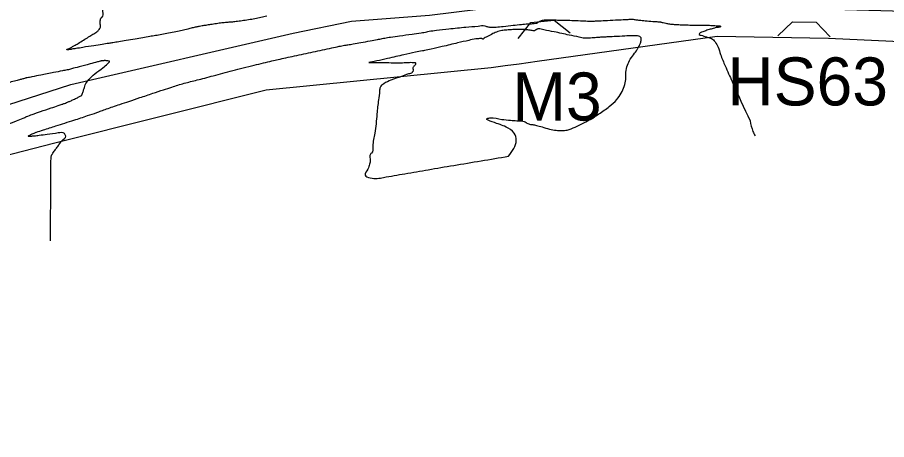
# Model space of a CAD drawing. Extents: x -478645 to -472650, y -1118147 to -1113892.
# Drawn here: x -477790.3 to -477609.4, y -1117492.2 to -1117404.3 of the extents above; entities that cross this region are included whole.
import ezdxf

# ---------------------------------------------------------------- set-up
doc = ezdxf.new("R2010")
doc.units = 0
for name, color, linetype in [('hospodářské sjezdy', 7, 'Continuous'), ('ObPÚ', 7, 'Continuous'), ('silnice', 7, 'Continuous'), ('TP_stavajicí_mosty', 7, 'Continuous'), ('Vrstevnice_vedlejsi', 7, 'Continuous')]:
    doc.layers.add(name, color=color, linetype=linetype)

msp = doc.modelspace()

# ---------------------------------------------------------------- linework, layer by layer
at = {"layer": 'hospodářské sjezdy'}
for p, q in [((-477632.071, -1117408.148), (-477629, -1117405.188)), ((-477629, -1117405.188), (-477624.116, -1117405.275)), ((-477624.116, -1117405.275), (-477621.152, -1117408.342))]:
    msp.add_line(p, q, dxfattribs=at)
at = {"layer": 'ObPÚ'}
msp.add_lwpolyline([(-477239.17, -1117423.45), (-477286.2, -1117422.09), (-477330.75, -1117420.42), (-477373.93, -1117418.61), (-477420.9, -1117417.49), (-477422.1, -1117417.56), (-477424.2, -1117417.6), (-477428.82, -1117417.33), (-477494.83, -1117414.18), (-477554.51, -1117411.78), (-477621.5, -1117408.68), (-477644.72, -1117408.28), (-477682.13, -1117413.46), (-477685.93, -1117414.02), (-477688.8, -1117414.36), (-477691.73, -1117414.77), (-477738.55, -1117419.44), (-477782.49, -1117430.5), (-477808.98, -1117437.26), (-477845.5, -1117449.81), (-477945.12, -1117479.46), (-478009.37, -1117499.81)], dxfattribs=at)
at = {"layer": 'silnice'}
msp.add_lwpolyline([(-478068.596, -1117511.329), (-477917.95, -1117462.993), (-477779.219, -1117418.245), (-477732.944, -1117407.585), (-477720.808, -1117405.048), (-477704.588, -1117403.835), (-477689.402, -1117401.926), (-477652.852, -1117401.691), (-477590.784, -1117403.37), (-477332.447, -1117414.279), (-477204.956, -1117416.797), (-477142.049, -1117416.797), (-477096.756, -1117410.083), (-477036.34, -1117397.174), (-476978.492, -1117379.033), (-476883.712, -1117344.626), (-476756.221, -1117298.47), (-476633.763, -1117254.832), (-476588.47, -1117242.245), (-476550.726, -1117234.692)], dxfattribs=at)
at = {"layer": 'TP_stavajicí_mosty'}
for p, q in [((-477686.134, -1117408.643), (-477683.444, -1117405.332)), ((-477683.444, -1117405.332), (-477678.585, -1117404.827)), ((-477678.585, -1117404.827), (-477675.271, -1117407.512))]:
    msp.add_line(p, q, dxfattribs=at)
at = {"layer": 'Vrstevnice_vedlejsi'}
for points in [[(-477738.437, -1117404.029), (-477739.644, -1117404.317), (-477740.902, -1117404.576), (-477742.212, -1117404.807), (-477743.574, -1117405.008), (-477744.784, -1117405.163), (-477745.843, -1117405.272), (-477746.75, -1117405.335), (-477747.765, -1117405.44), (-477748.889, -1117405.588), (-477750.122, -1117405.779), (-477751.125, -1117405.935), (-477751.899, -1117406.057), (-477752.443, -1117406.144), (-477753.121, -1117406.287), (-477753.932, -1117406.486), (-477754.876, -1117406.74), (-477756.014, -1117407.008), (-477757.345, -1117407.29), (-477758.869, -1117407.586), (-477760.282, -1117407.848), (-477761.586, -1117408.076), (-477762.779, -1117408.271), (-477764.195, -1117408.506), (-477765.833, -1117408.782), (-477767.693, -1117409.1), (-477769.227, -1117409.357), (-477770.435, -1117409.552), (-477771.317, -1117409.687), (-477772.649, -1117409.894), (-477774.432, -1117410.176), (-477776.667, -1117410.531), (-477778.181, -1117410.775), (-477778.976, -1117410.906), (-477779.051, -1117410.926), (-477779.226, -1117410.956), (-477779.5, -1117410.994), (-477779.875, -1117411.041), (-477780.06, -1117411.041), (-477780.055, -1117410.994), (-477779.86, -1117410.9), (-477779.638, -1117410.792), (-477779.387, -1117410.669), (-477779.109, -1117410.532), (-477778.54, -1117410.207), (-477777.68, -1117409.694), (-477776.529, -1117408.994), (-477775.501, -1117408.359), (-477774.593, -1117407.79), (-477773.808, -1117407.287), (-477773.289, -1117406.801), (-477773.038, -1117406.331), (-477773.053, -1117405.877), (-477773.061, -1117405.472), (-477773.06, -1117405.117), (-477773.052, -1117404.81), (-477772.996, -1117404.569), (-477772.893, -1117404.395), (-477772.742, -1117404.287), (-477772.508, -1117403.024), (-477772.191, -1117400.605), (-477771.79, -1117397.031), (-477771.568, -1117390.931), (-477771.525, -1117382.305), (-477771.66, -1117371.152), (-477771.923, -1117360.756), (-477772.313, -1117351.115), (-477772.829, -1117342.231), (-477773.795, -1117334.825), (-477775.208, -1117328.897), (-477777.071, -1117324.449), (-477778.387, -1117319.217), (-477779.156, -1117313.201), (-477779.379, -1117306.402), (-477780.166, -1117299.691), (-477781.516, -1117293.068), (-477783.429, -1117286.534), (-477785.561, -1117281.406), (-477787.912, -1117277.684), (-477790.482, -1117275.368), (-477792.967, -1117272.524), (-477795.368, -1117269.152), (-477797.684, -1117265.251), (-477800.572, -1117260.279), (-477804.033, -1117254.234), (-477808.066, -1117247.117), (-477810.645, -1117241.138), (-477811.77, -1117236.296), (-477811.44, -1117232.593), (-477811.873, -1117226.914), (-477813.068, -1117219.259), (-477815.026, -1117209.63), (-477818.888, -1117199.125), (-477824.655, -1117187.744), (-477832.328, -1117175.488), (-477837.806, -1117166.958), (-477841.092, -1117162.155)], [(-477714.4, -1117408.695), (-477713.88, -1117408.578), (-477712.673, -1117408.383), (-477710.778, -1117408.11), (-477708.197, -1117407.759), (-477706.312, -1117407.486), (-477705.124, -1117407.291), (-477704.632, -1117407.174), (-477703.11, -1117406.969), (-477700.556, -1117406.677), (-477696.971, -1117406.297), (-477694.461, -1117406.081), (-477693.026, -1117406.03), (-477692.665, -1117406.142), (-477692.424, -1117406.219), (-477692.302, -1117406.259), (-477692.3, -1117406.263), (-477692.187, -1117406.278), (-477691.963, -1117406.303), (-477691.628, -1117406.339), (-477690.714, -1117406.286), (-477689.219, -1117406.145), (-477687.144, -1117405.916), (-477685.437, -1117405.745), (-477684.098, -1117405.632), (-477683.125, -1117405.577), (-477682.45, -1117405.507), (-477682.072, -1117405.423), (-477681.99, -1117405.325), (-477681.825, -1117405.211), (-477681.575, -1117405.081), (-477681.24, -1117404.935), (-477680.853, -1117404.842), (-477680.414, -1117404.802), (-477679.923, -1117404.814), (-477679.548, -1117404.813), (-477679.29, -1117404.8), (-477679.149, -1117404.774), (-477679.013, -1117404.765), (-477678.883, -1117404.774), (-477678.757, -1117404.801), (-477678.434, -1117404.819), (-477677.915, -1117404.828), (-477677.198, -1117404.829), (-477676.088, -1117404.858), (-477674.584, -1117404.915), (-477672.688, -1117405), (-477671.361, -1117405.051), (-477670.605, -1117405.069)], [(-477670.605, -1117405.069), (-477670.42, -1117405.054), (-477669.569, -1117405.008), (-477668.052, -1117404.93), (-477665.87, -1117404.82), (-477664.263, -1117404.739), (-477663.229, -1117404.687), (-477662.77, -1117404.664), (-477662.351, -1117404.67), (-477661.971, -1117404.705), (-477661.63, -1117404.769), (-477660.869, -1117404.857), (-477659.688, -1117404.968), (-477658.087, -1117405.103), (-477657.02, -1117405.192), (-477656.486, -1117405.237), (-477656.485, -1117405.237), (-477656.304, -1117405.284), (-477655.941, -1117405.377), (-477655.397, -1117405.516), (-477654.626, -1117405.633), (-477653.628, -1117405.726), (-477652.401, -1117405.796), (-477651.078, -1117405.847), (-477649.657, -1117405.88), (-477648.14, -1117405.894), (-477646.935, -1117405.914), (-477646.043, -1117405.939), (-477645.464, -1117405.97), (-477644.928, -1117406.009), (-477644.435, -1117406.058), (-477643.985, -1117406.115), (-477643.977, -1117406.213), (-477644.411, -1117406.352), (-477645.287, -1117406.531), (-477646.167, -1117406.761), (-477647.052, -1117407.044), (-477647.941, -1117407.379), (-477648.398, -1117407.649), (-477648.423, -1117407.855), (-477648.014, -1117407.997), (-477647.457, -1117408.181), (-477646.749, -1117408.406), (-477645.891, -1117408.674), (-477645.146, -1117409.362), (-477644.514, -1117410.473), (-477643.994, -1117412.004), (-477643.021, -1117414.39), (-477641.596, -1117417.631), (-477637.841, -1117425.821)], [(-477688.123, -1117433.202), (-477686.515, -1117429.862), (-477686.949, -1117428.387), (-477688.622, -1117427.107), (-477691.532, -1117426.022), (-477692.655, -1117425.393), (-477691.991, -1117425.222), (-477689.539, -1117425.508), (-477687.673, -1117425.698), (-477686.393, -1117425.793), (-477685.699, -1117425.792), (-477685.119, -1117425.872), (-477684.653, -1117426.034), (-477684.3, -1117426.276), (-477683.922, -1117426.453), (-477683.517, -1117426.562), (-477683.086, -1117426.605), (-477682.29, -1117426.781), (-477681.131, -1117427.09), (-477679.607, -1117427.532), (-477678.229, -1117427.788), (-477676.995, -1117427.857), (-477675.907, -1117427.741), (-477674.26, -1117427.121), (-477672.055, -1117425.998), (-477669.292, -1117424.371), (-477667.14, -1117422.837), (-477665.597, -1117421.396), (-477664.665, -1117420.047), (-477664.037, -1117418.642), (-477663.712, -1117417.18), (-477663.691, -1117415.663), (-477663.377, -1117414.253), (-477662.77, -1117412.951), (-477661.87, -1117411.756), (-477661.194, -1117410.712), (-477660.742, -1117409.818), (-477660.514, -1117409.074), (-477660.521, -1117408.548), (-477660.763, -1117408.24), (-477661.242, -1117408.149), (-477662.296, -1117408.126), (-477663.927, -1117408.171), (-477666.133, -1117408.283), (-477667.669, -1117408.361), (-477668.535, -1117408.405), (-477668.73, -1117408.414), (-477669.161, -1117408.445), (-477669.829, -1117408.497), (-477670.734, -1117408.57), (-477671.397, -1117408.615), (-477671.819, -1117408.634), (-477671.999, -1117408.626), (-477672.142, -1117408.621), (-477672.248, -1117408.618), (-477672.316, -1117408.618), (-477673.399, -1117408.398), (-477675.497, -1117407.957), (-477678.61, -1117407.297), (-477680.733, -1117406.865), (-477681.866, -1117406.663), (-477682.009, -1117406.69), (-477682.156, -1117406.735), (-477682.305, -1117406.8), (-477682.456, -1117406.883), (-477682.571, -1117406.955), (-477682.649, -1117407.014), (-477682.69, -1117407.061), (-477682.718, -1117407.092), (-477682.731, -1117407.108), (-477682.732, -1117407.108), (-477682.959, -1117407.07), (-477683.412, -1117406.995), (-477684.092, -1117406.883), (-477684.811, -1117406.813), (-477685.567, -1117406.784), (-477686.362, -1117406.796), (-477687.244, -1117406.835), (-477688.211, -1117406.9), (-477689.265, -1117406.991), (-477690.323, -1117407.246), (-477691.387, -1117407.666), (-477692.456, -1117408.25), (-477693.178, -1117408.625), (-477693.552, -1117408.792), (-477693.578, -1117408.749), (-477693.615, -1117408.715), (-477693.662, -1117408.688), (-477693.72, -1117408.67), (-477693.951, -1117408.679), (-477694.354, -1117408.713), (-477694.93, -1117408.774), (-477696.381, -1117409.069), (-477698.707, -1117409.598), (-477701.907, -1117410.36), (-477704.195, -1117410.889), (-477705.572, -1117411.185)], [(-477783.419, -1117450.824), (-477783.385, -1117443.847), (-477783.344, -1117437.193), (-477783.307, -1117433.697), (-477783.275, -1117433.361), (-477783.245, -1117433.129), (-477783.218, -1117433.001), (-477783.192, -1117432.977), (-477783.169, -1117432.951), (-477783.147, -1117432.922), (-477783.127, -1117432.89), (-477783.109, -1117432.856), (-477783.092, -1117432.82), (-477783.076, -1117432.783), (-477782.922, -1117432.552), (-477782.631, -1117432.129), (-477782.201, -1117431.512), (-477781.664, -1117430.783), (-477781.019, -1117429.941), (-477780.266, -1117428.987), (-477780.53, -1117428.456), (-477781.81, -1117428.35), (-477784.107, -1117428.667), (-477785.776, -1117428.888), (-477786.815, -1117429.013), (-477787.226, -1117429.04), (-477787.571, -1117429.053), (-477787.848, -1117429.051), (-477788.059, -1117429.033), (-477788.029, -1117428.944), (-477787.757, -1117428.782), (-477787.246, -1117428.548), (-477786.835, -1117428.368), (-477786.525, -1117428.243), (-477786.317, -1117428.173), (-477784.916, -1117427.721), (-477782.322, -1117426.887), (-477778.536, -1117425.672), (-477775.697, -1117424.742), (-477773.807, -1117424.097), (-477772.864, -1117423.738), (-477771.744, -1117423.335), (-477770.448, -1117422.886), (-477768.974, -1117422.392), (-477767.095, -1117421.76), (-477764.81, -1117420.99), (-477762.118, -1117420.08), (-477759.905, -1117419.343), (-477758.17, -1117418.777), (-477756.914, -1117418.384), (-477755.618, -1117418.008), (-477754.281, -1117417.651), (-477752.904, -1117417.311), (-477751.327, -1117416.903), (-477749.55, -1117416.426), (-477747.572, -1117415.881), (-477745.496, -1117415.333), (-477743.321, -1117414.782), (-477741.048, -1117414.229), (-477739.073, -1117413.753), (-477737.397, -1117413.355), (-477736.019, -1117413.035), (-477734.443, -1117412.684), (-477732.669, -1117412.301), (-477730.696, -1117411.887), (-477728.742, -1117411.469), (-477726.807, -1117411.047), (-477724.891, -1117410.622), (-477723.376, -1117410.303), (-477722.261, -1117410.09), (-477721.548, -1117409.983), (-477720.415, -1117409.793), (-477718.862, -1117409.521), (-477716.891, -1117409.167), (-477715.404, -1117408.891), (-477714.4, -1117408.695)], [(-477705.572, -1117411.185), (-477706.038, -1117411.248), (-477707.477, -1117411.545), (-477709.889, -1117412.075), (-477713.274, -1117412.839), (-477715.534, -1117413.349), (-477716.668, -1117413.604), (-477716.676, -1117413.606), (-477716.75, -1117413.617), (-477716.89, -1117413.638), (-477717.096, -1117413.669), (-477717.175, -1117413.687), (-477717.126, -1117413.691), (-477716.95, -1117413.682), (-477716.808, -1117413.675), (-477716.7, -1117413.668), (-477716.626, -1117413.663), (-477715.907, -1117413.669), (-477714.541, -1117413.685), (-477712.53, -1117413.712), (-477710.845, -1117413.713), (-477709.486, -1117413.686), (-477708.454, -1117413.633), (-477707.773, -1117413.662), (-477707.444, -1117413.774), (-477707.467, -1117413.968), (-477707.548, -1117414.166), (-477707.687, -1117414.367), (-477707.884, -1117414.573), (-477707.993, -1117414.774), (-477708.012, -1117414.971), (-477707.943, -1117415.164), (-477707.915, -1117415.314), (-477707.929, -1117415.421), (-477707.985, -1117415.486), (-477708.043, -1117415.56), (-477708.103, -1117415.644), (-477708.166, -1117415.738), (-477708.933, -1117416.051), (-477710.403, -1117416.584), (-477712.577, -1117417.335), (-477714.059, -1117418.09), (-477714.848, -1117418.847), (-477714.944, -1117419.608), (-477715.161, -1117421.452), (-477715.5, -1117424.382), (-477715.959, -1117428.397), (-477716.339, -1117431.126), (-477716.641, -1117432.572), (-477716.863, -1117432.733), (-477716.978, -1117433.03), (-477716.984, -1117433.465), (-477716.882, -1117434.036), (-477717.013, -1117434.837), (-477717.376, -1117435.868), (-477717.971, -1117437.128), (-477716.886, -1117437.707), (-477714.122, -1117437.606), (-477709.678, -1117436.825), (-477704.814, -1117435.988), (-477699.53, -1117435.096), (-477688.123, -1117433.202)], [(-477824.901, -1117439.31), (-477824.387, -1117439.092), (-477823.138, -1117438.597), (-477821.155, -1117437.828), (-477818.437, -1117436.783), (-477816.34, -1117435.969), (-477814.865, -1117435.386), (-477814.012, -1117435.034), (-477813.235, -1117434.715), (-477812.535, -1117434.43), (-477811.911, -1117434.178), (-477810.759, -1117433.657), (-477809.079, -1117432.868), (-477806.872, -1117431.81), (-477804.903, -1117430.911), (-477803.172, -1117430.171), (-477801.681, -1117429.591), (-477800.47, -1117429.18), (-477799.54, -1117428.938), (-477798.891, -1117428.866), (-477797.518, -1117428.458), (-477795.42, -1117427.716), (-477792.599, -1117426.639), (-477790.491, -1117425.817), (-477789.095, -1117425.25), (-477788.413, -1117424.938), (-477787.221, -1117424.482), (-477785.519, -1117423.88), (-477783.308, -1117423.134), (-477781.799, -1117422.626), (-477780.995, -1117422.356), (-477780.893, -1117422.323), (-477780.673, -1117422.243), (-477780.334, -1117422.116), (-477779.877, -1117421.942), (-477779.306, -1117421.697), (-477778.622, -1117421.381), (-477777.825, -1117420.995), (-477777.273, -1117420.714), (-477776.968, -1117420.541), (-477776.908, -1117420.473), (-477776.761, -1117420.085), (-477776.528, -1117419.374), (-477776.208, -1117418.342), (-477775.433, -1117417.229), (-477774.203, -1117416.037), (-477772.518, -1117414.766), (-477771.508, -1117413.892), (-477771.173, -1117413.417), (-477771.514, -1117413.341), (-477771.825, -1117413.296), (-477772.107, -1117413.281), (-477772.359, -1117413.298), (-477772.554, -1117413.314), (-477772.693, -1117413.328), (-477772.775, -1117413.34), (-477772.837, -1117413.35), (-477772.88, -1117413.356), (-477772.902, -1117413.36), (-477773.677, -1117413.566), (-477775.204, -1117413.974), (-477777.485, -1117414.585), (-477779.042, -1117414.997), (-477779.876, -1117415.21), (-477779.988, -1117415.224), (-477780.954, -1117415.411), (-477782.776, -1117415.772), (-477785.454, -1117416.307), (-477787.28, -1117416.667), (-477788.255, -1117416.851), (-477788.379, -1117416.861), (-477788.576, -1117416.905), (-477788.848, -1117416.983), (-477789.192, -1117417.096), (-477789.875, -1117417.287), (-477790.896, -1117417.555), (-477792.255, -1117417.901), (-477793.223, -1117418.177), (-477793.801, -1117418.384), (-477793.988, -1117418.52), (-477794.441, -1117418.674), (-477795.159, -1117418.845), (-477796.142, -1117419.033), (-477797.208, -1117419.25), (-477798.354, -1117419.496), (-477799.582, -1117419.771), (-477800.586, -1117419.99), (-477801.364, -1117420.153), (-477801.918, -1117420.26), (-477802.397, -1117420.33), (-477802.804, -1117420.365), (-477803.136, -1117420.363), (-477803.451, -1117420.298), (-477803.75, -1117420.17), (-477804.032, -1117419.979), (-477804.244, -1117419.751), (-477804.386, -1117419.488)], [(-477637.841, -1117425.821), (-477637.256, -1117428.024), (-477636.819, -1117428.94)]]:
    msp.add_spline(points, degree=3, dxfattribs=at)

# ---------------------------------------------------------------- texts
at = {"layer": 'hospodářské sjezdy'}
msp.add_text('HS63', height=10, rotation=359.99999, dxfattribs=at).set_placement((-477642.594, -1117422.613))
at = {"layer": 'TP_stavajicí_mosty'}
msp.add_text('M3', height=10, rotation=359.99999, dxfattribs=at).set_placement((-477687.303, -1117425.751))

doc.saveas('drawing.dxf')
